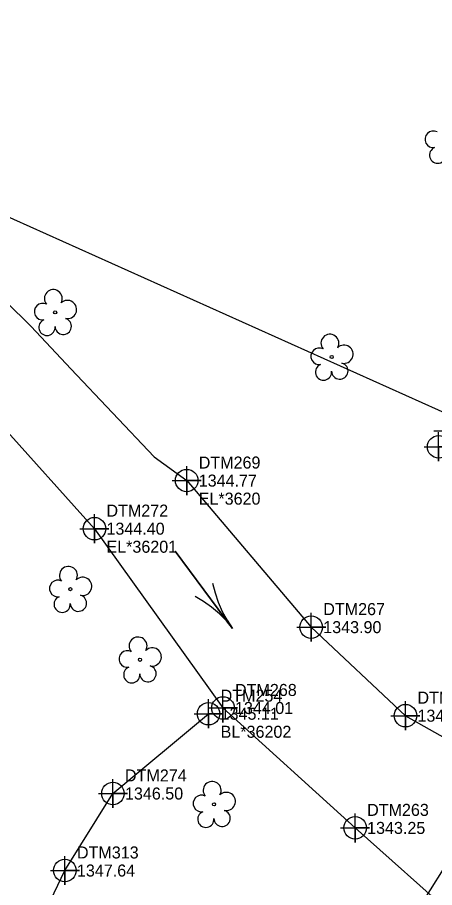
# Model space of a CAD drawing. Extents: x 1435573 to 1437263, y 981340 to 982884.
# Drawn here: x 1436076 to 1436162.6, y 982369.2 to 982550 of the extents above; entities that cross this region are included whole.
import ezdxf

# ---------------------------------------------------------------- set-up
doc = ezdxf.new("R2010")
doc.units = 0
for name, color, linetype in [('Exist Horizontal Baseline Alignment Station Label', 7, 'Continuous'), ('Exist Hydro Jurisdictional Stream or Body of Water', 7, 'Continuous'), ('Exist Hydro River Flow Arrow CELL', 7, 'Continuous'), ('Exist Hydro Stream or Body of Water Cogo Comment', 7, 'Continuous'), ('Exist Hydro Stream or Body of Water Cogo Elevation', 7, 'Continuous'), ('Exist Hydro Stream or Body of Water Cogo Number', 7, 'Continuous'), ('Exist Hydro Stream or Body of Water Cogo Point CELL', 7, 'Continuous'), ('Exist Right of Way Line', 7, 'Continuous'), ('Exist Vegetation Tree CELL', 7, 'Continuous')]:
    doc.layers.add(name, color=color, linetype=linetype)

# ---------------------------------------------------------------- blocks, each defined once
blk = doc.blocks.new('EXIST HYDRO RIVER FLOW ARROW')
at = {"layer": 'Exist Hydro River Flow Arrow CELL'}
blk.add_line((0, 0), (0, 0), dxfattribs=at)
blk.add_lwpolyline([(0, 0.04575), (0.03775, 0.03), (0.07725, 0.01725), (0.118, 0.00775), (0.159, 0.0015), (0.2, 0), (-0.2, 0), (0.2, 0), (0.159, -0.0015), (0.118, -0.00775), (0.07725, -0.01725), (0.03775, -0.03), (0, -0.04575)], dxfattribs=at)

msp = doc.modelspace()

# ---------------------------------------------------------------- linework, layer by layer
at = {"layer": 'Exist Horizontal Baseline Alignment Station Label'}
msp.add_line((1436220.79, 982442.59), (1435992.65, 982545.09), dxfattribs=at)
at = {"layer": 'Exist Hydro Jurisdictional Stream or Body of Water'}
for points in [[(1435993.51, 982575.54), (1436004.62, 982570.21), (1436016.87, 982565.15), (1436031.87, 982555.63), (1436045.15, 982542.72), (1436048.39, 982532.48), (1436050.69, 982519.28), (1436057.99, 982507.82), (1436068.19, 982496.23), (1436078.82, 982485.77), (1436087.08, 982476.93)], [(1436087.08, 982476.93), (1436104.4, 982458.69), (1436111.15, 982453.74)], [(1436091.98, 982443.75), (1436072.03, 982465.87)], [(1436111.15, 982453.74), (1436137.02, 982423.29), (1436156.59, 982404.89), (1436183.39, 982389.76), (1436202.59, 982381.74), (1436230.76, 982371.66), (1436265.68, 982349.11), (1436287.96, 982335.57), (1436310.38, 982331.33), (1436342.49, 982321.19), (1436376.37, 982319.71), (1436409.66, 982315.5), (1436442.82, 982320.6), (1436463.49, 982320.37), (1436497.53, 982330.71), (1436550.33, 982336.59), (1436616.17, 982332.31)], [(1436091.98, 982443.75), (1436118.69, 982406.49), (1436146.13, 982381.57), (1436167.28, 982362.75), (1436182.9, 982351.8), (1436221.27, 982335.17), (1436252.29, 982318.28), (1436286.21, 982313.63), (1436313.86, 982303.99), (1436344.05, 982299.63), (1436382.91, 982293.64), (1436445.46, 982294.47), (1436493.31, 982296.22), (1436523.01, 982301.22), (1436526.68, 982304.85), (1436546.5, 982314.76), (1436602.72, 982314.24)], [(1435868.19, 982015.59), (1435900.37, 982051.1), (1435890.46, 982068.11), (1435899.75, 982073.74), (1435922.56, 982111.64), (1435976.46, 982187.79), (1435990.17, 982221.39), (1436012.44, 982254.73), (1436035.55, 982280.88), (1436050.71, 982320.86), (1436073.43, 982346.77), (1436085.85, 982372.72), (1436095.83, 982388.72), (1436115.7, 982405.3)]]:
    msp.add_lwpolyline(points, dxfattribs=at)
at = {"layer": 'Exist Hydro Stream or Body of Water Cogo Point CELL'}
for points in [[(1436162.49, 982464.1), (1436168.49, 982464.1), (1436165.49, 982464.1), (1436165.49, 982461.1), (1436165.49, 982467.1)], [(1436160.49, 982460.77), (1436166.49, 982460.77), (1436163.49, 982460.77), (1436163.49, 982457.77), (1436163.49, 982463.77)], [(1436108.15, 982453.74), (1436114.15, 982453.74), (1436111.15, 982453.74), (1436111.15, 982450.74), (1436111.15, 982456.74)], [(1436088.98, 982443.75), (1436094.98, 982443.75), (1436091.98, 982443.75), (1436091.98, 982440.75), (1436091.98, 982446.75)], [(1436134.02, 982423.29), (1436140.02, 982423.29), (1436137.02, 982423.29), (1436137.02, 982420.29), (1436137.02, 982426.29)], [(1436112.7, 982405.3), (1436118.7, 982405.3), (1436115.7, 982405.3), (1436115.7, 982402.3), (1436115.7, 982408.3)], [(1436115.69, 982406.49), (1436121.69, 982406.49), (1436118.69, 982406.49), (1436118.69, 982403.49), (1436118.69, 982409.49)], [(1436153.59, 982404.89), (1436159.59, 982404.89), (1436156.59, 982404.89), (1436156.59, 982401.89), (1436156.59, 982407.89)], [(1436092.83, 982388.72), (1436098.83, 982388.72), (1436095.83, 982388.72), (1436095.83, 982385.72), (1436095.83, 982391.72)], [(1436143.13, 982381.57), (1436149.13, 982381.57), (1436146.13, 982381.57), (1436146.13, 982378.57), (1436146.13, 982384.57)], [(1436082.85, 982372.72), (1436088.85, 982372.72), (1436085.85, 982372.72), (1436085.85, 982369.72), (1436085.85, 982375.72)]]:
    msp.add_lwpolyline(points, dxfattribs=at)
for centre in [(1436163.49, 982460.77), (1436111.15, 982453.74), (1436091.98, 982443.75), (1436137.02, 982423.29), (1436118.69, 982406.49), (1436115.7, 982405.3), (1436156.59, 982404.89), (1436095.83, 982388.72), (1436146.13, 982381.57), (1436085.85, 982372.72)]:
    msp.add_circle(centre, 2.34, dxfattribs=at)
at = {"layer": 'Exist Right of Way Line'}
msp.add_line((1436152.59, 982354), (1436196.89, 982424.9), dxfattribs=at)
at = {"layer": 'Exist Vegetation Tree CELL'}
for p, q in [((1436083.83, 982488.7), (1436083.83, 982488.7)), ((1436141.28, 982479.41), (1436141.28, 982479.41)), ((1436086.98, 982431.17), (1436086.98, 982431.17)), ((1436101.44, 982416.51), (1436101.44, 982416.51)), ((1436116.83, 982386.48), (1436116.83, 982386.48))]:
    msp.add_line(p, q, dxfattribs=at)
for centre in [(1436083.83, 982488.7), (1436141.28, 982479.41), (1436086.98, 982431.17), (1436101.44, 982416.51), (1436116.83, 982386.48)]:
    msp.add_circle(centre, 0.326, dxfattribs=at)
for centre, radius, start, end in [((1436162.37, 982524.64), 1.73, 62.6636, 279.3457), ((1436163.28, 982521.36), 1.69, 111.5671, 6.231), ((1436083.44, 982491.57), 1.86, 330.1651, 219.7134), ((1436086.38, 982489.29), 1.9, 257.1011, 134.1999), ((1436081.22, 982488.85), 1.73, 62.6636, 279.3457), ((1436085.5, 982485.8), 1.7, 181.2822, 74.56), ((1436082.12, 982485.58), 1.69, 111.5671, 6.231), ((1436140.9, 982482.28), 1.86, 330.1651, 219.7134), ((1436143.83, 982480), 1.9, 257.1011, 134.1999), ((1436138.68, 982479.56), 1.73, 62.6636, 279.3457), ((1436139.58, 982476.29), 1.69, 111.5671, 6.231), ((1436142.96, 982476.51), 1.7, 181.2822, 74.56), ((1436086.59, 982434.04), 1.86, 330.1651, 219.7134), ((1436084.37, 982431.32), 1.73, 62.6636, 279.3457), ((1436089.53, 982431.76), 1.9, 257.1011, 134.1999), ((1436085.27, 982428.05), 1.69, 111.5671, 6.231), ((1436088.65, 982428.27), 1.7, 181.2822, 74.56), ((1436101.05, 982419.38), 1.86, 330.1651, 219.7134), ((1436103.99, 982417.1), 1.9, 257.1011, 134.1999), ((1436098.83, 982416.66), 1.73, 62.6636, 279.3457), ((1436099.74, 982413.39), 1.69, 111.5671, 6.231), ((1436103.11, 982413.61), 1.7, 181.2822, 74.56), ((1436116.44, 982389.36), 1.86, 330.1651, 219.7134), ((1436114.22, 982386.64), 1.73, 62.6636, 279.3457), ((1436119.37, 982387.07), 1.9, 257.1011, 134.1999), ((1436115.12, 982383.36), 1.69, 111.5671, 6.231), ((1436118.5, 982383.58), 1.7, 181.2822, 74.56)]:
    msp.add_arc(centre, radius, start, end, dxfattribs=at)

# ---------------------------------------------------------------- block references
at = {"layer": 'Exist Hydro River Flow Arrow CELL', "xscale": 50, "yscale": 50, "rotation": -53.227753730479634}
msp.add_blockref('EXIST HYDRO RIVER FLOW ARROW', (1436114.71, 982431.04), dxfattribs=at)

# ---------------------------------------------------------------- texts
at = {"layer": 'Exist Hydro Stream or Body of Water Cogo Comment'}
for s, p in [('EL*3620', (1436113.65, 982448.74)), ('EL*36201', (1436094.48, 982438.75)), ('BL*36202', (1436118.2, 982400.3))]:
    msp.add_text(s, height=2.5, dxfattribs=at).set_placement(p)
at = {"layer": 'Exist Hydro Stream or Body of Water Cogo Elevation'}
for s, p in [('1344.77', (1436113.65, 982452.49)), ('1344.40', (1436094.48, 982442.5)), ('1343.90', (1436139.52, 982422.04)), ('1344.01', (1436121.19, 982405.24)), ('1345.11', (1436118.2, 982404.05)), ('1343.92', (1436159.09, 982403.64)), ('1346.50', (1436098.33, 982387.47)), ('1343.25', (1436148.63, 982380.32)), ('1347.64', (1436088.35, 982371.47))]:
    msp.add_text(s, height=2.5, dxfattribs=at).set_placement(p)
at = {"layer": 'Exist Hydro Stream or Body of Water Cogo Number'}
for s, p in [('DTM269', (1436113.65, 982456.24)), ('DTM272', (1436094.48, 982446.25)), ('DTM267', (1436139.52, 982425.79)), ('DTM268', (1436121.19, 982408.99)), ('DTM254', (1436118.2, 982407.8)), ('DTM265', (1436159.09, 982407.39)), ('DTM274', (1436098.33, 982391.22)), ('DTM263', (1436148.63, 982384.07)), ('DTM313', (1436088.35, 982375.22))]:
    msp.add_text(s, height=2.5, dxfattribs=at).set_placement(p)

doc.saveas('drawing.dxf')
